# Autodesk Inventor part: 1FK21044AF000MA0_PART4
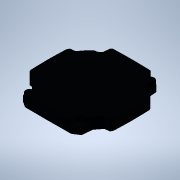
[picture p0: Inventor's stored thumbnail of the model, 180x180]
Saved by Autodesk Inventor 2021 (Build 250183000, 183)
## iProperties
Created: 2025-04
Part Number: 1FK21044AF000MA0_PART4
Material: Generic
Catalog Web Link: www.3dfindit.com
Description: -Servo synchronous motor
Document SubType Name: Modeling
Designer: psAdmin
Mass: 55.5405 g
Surface Area: 149.572 cm^2
Volume: 55.5405 cm^3
Density: 1 g/cm^3
Appearance: PSOLRGB-38-46-56
Category: PARTsolutions
Title: 1FK21044AF000MA0_PART4
Author: Cadenas PARTsolutions
Comments: Servo synchronous motor
Sending System: PARTsolutions
Preprocessor: ST-DEVELOPER v19.3
PSOL_IDENT_0: {$CADENAS_DATA/23d-libs/siemens_ag/_cat_/39/c4/1fk21044af000ma0.prj},213 {VTYP=3D},{NB=1FK21044AF000
PSOL_IDENT_1: MA0_PART4},{LINA=1FK21044AF000MA0_PART4},{NN=1FK21044AF000MA0_PART4},{NOPRJ=TRUE},{DATE=19.08.2025 1
PSOL_IDENT_2: 4:00:33},{GEOMDATE=30.07.2025 02:02:22},{VERSION=},{LINEID=10},{WBVAR=},{WBNUMERIC=}  {NB=1FK21044AF
PSOL_IDENT_3: 000MA0_PART4},{LINA=1FK21044AF000MA0_PART4},{KT=DUMMY},{PREVIEW=../../../_pool_/cb/72/p_d211_xx_0043
PSOL_IDENT_4: 4j.png},{DESCSHORT=SIMOTICS S-1FK2 HD, SINAMICS S210 3AC 400V-480V, 1.27 Nm, 3000 rpm},{DESCLONG=SIM
PSOL_IDENT_5: OTICS S-1FK2 HD servo motor M0=1.27 Nm; PN = 0.4 kW at nN=3000 rpm (380-480 V); PN = 0.2 kW at nN=15
PSOL_IDENT_6: 00 rpm (200-240 V); degree of protection IP64; cylindrical shaft D19x40mm; absolute encoder 22-bit +
PSOL_IDENT_7: 12-bit multiturn (encoder AM22DQC); with OCC interface; plug size M17, rotatable; SIMOTICS S-1FK2 s
PSOL_IDENT_8: ervomotorfor a wide range of uses in industrial environments. SIMOTICS S‑1FK2 servomotors are compac
PSOL_IDENT_9: t synchronous motors with a high dynamic performance that set themselves apart as a result of their
PSOL_IDENT_10: high power density, degree of protection and overload capability. The motors are available in two va
PSOL_IDENT_11: riants: as High Dynamic variant (highest dynamic performance as a result of the low intrinsic moment
PSOL_IDENT_12: of inertia for applications demanding a high dynamic performance with low moved masses) - and as Co
PSOL_IDENT_13: mpact variant (precise and stable closed-loop control for medium up to large moved masses as a resul
PSOL_IDENT_14: t of a medium intrinsic moment of inertia). SIMOTICSS‑1FK2 servomotors fully exploit their strengths
PSOL_IDENT_15: in a system with the SINAMICSS210 frequency converter and simple connection using the one cable con
PSOL_IDENT_16: nection (OCC). Advantages include the short control and positioning times, fast and precise correcti
PSOL_IDENT_17: on of disturbing quantities as well as stable control with a high dynamic performance. The servo mot
PSOL_IDENT_18: ors can be configured to address a wide range of requirements. For example with and without holding
PSOL_IDENT_19: brake, IP64 or IP65 degree of protection, singleturn or multiturn absolute encoders - to name just a
PSOL_IDENT_20: few. Further, the servomotors are available in different shaft heights extending from 20 to 100. A
PSOL_IDENT_21: shaft sealing ring is available to achieve an IP65 degree of protection and for subsequent mounting
PSOL_IDENT_22: at the motor or as spare part. SIMOTICS - the optimum motor for each and every motion control applic
PSOL_IDENT_23: ation.},{INTNO=804766906428},{SUPPLIERALTNO=1FK2104-4AF00-0MA0},{MANUID=1FK21044AF000MA0},{MANUNAME=
PSOL_IDENT_24: Siemens},{MANUTYPEDESC=Synchronous motor 1FK2-HD 1.27 NM},{AAU732=SIMOTICS},{AAO057=S-1FK2},{AAU734=
PSOL_IDENT_25: SIMOTICS S-1FK2 HD servo motor M0=1.27 Nm; PN = 0.4 kW at nN=3000 rpm (380-480 V); PN = 0.2 kW at nN=
PSOL_IDENT_26: 1500 rpm (200-240 V); degree of protection IP64; cylindrical shaft D19x40mm; absolute encoder 22-bit
PSOL_IDENT_27: + 12-bit multiturn (encoder AM22DQC); with OCC interface; plug size M17, rotatable;},{AAW338=Synchr
PSOL_IDENT_28: onous motor 1FK2-HD 1.27 NM},{AAO742=SIMOTICS},{AAO663=4042948693322},{NOCUPEROU=1},{PRICEQUANTITY=1
PSOL_IDENT_29: },{QUANTITYMIN=1},{QUANTITYINT=1},{CTN=85015100},{COO=DE},{AAO676=1FK2104-4AF00-0MA0},{AAO677=Siemen
PSOL_IDENT_30: s AG},{ORDERUNIT=C62},{CONTENTUNIT=C62}
NB: 1FK21044AF000MA0_PART4
NT: Servo synchronous motor
NBSYN: $MANUID._PART4
LINA: 1FK21044AF000MA0_PART4
CATALOG: SIEMENS
PREVIEW: ../../../_pool_/cb/72/p_d211_xx_00434j.png
DESCSHORT: SIMOTICS S-1FK2 HD, SINAMICS S210 3AC 400V-480V, 1.27 Nm, 3000 rpm
DESCLONG: SIMOTICS S-1FK2 HD servo motor M0=1.27 Nm; PN = 0.4 kW at nN=3000 rpm (380-480 V); PN = 0.2 kW at nN=1500 rpm (200-240 V); degree of protection IP64; cylindrica
INTNO: 804766906428
SUPPLIERALTNO: 1FK2104-4AF00-0MA0
MANUID: 1FK21044AF000MA0
MANUNAME: Siemens
MANUTYPEDESC: Synchronous motor 1FK2-HD 1.27 NM
AAU732: SIMOTICS
AAO057: S-1FK2
AAU734: SIMOTICS S-1FK2 HD servo motor M0=1.27 Nm; PN = 0.4 kW at nN=3000 rpm (380-480 V); PN = 0.2 kW at nN=1500 rpm (200-240 V); degree of protection IP64; cylindrica
AAW338: Synchronous motor 1FK2-HD 1.27 NM
AAO742: SIMOTICS
AAO663: 4042948693322.0
NOCUPEROU: 1
PRICEQUANTITY: 1
QUANTITYMIN: 1
QUANTITYINT: 1
CTN: 85015100
COO: DE
ARTICLENO: 1FK21044AF000MA0_PART4
BOMINFO: 1FK21044AF000MA0_PART4
CREATOR: CADENAS GmbH
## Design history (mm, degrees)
feature "2025_04_17_15_01_27_0944"
body "Solid1"
